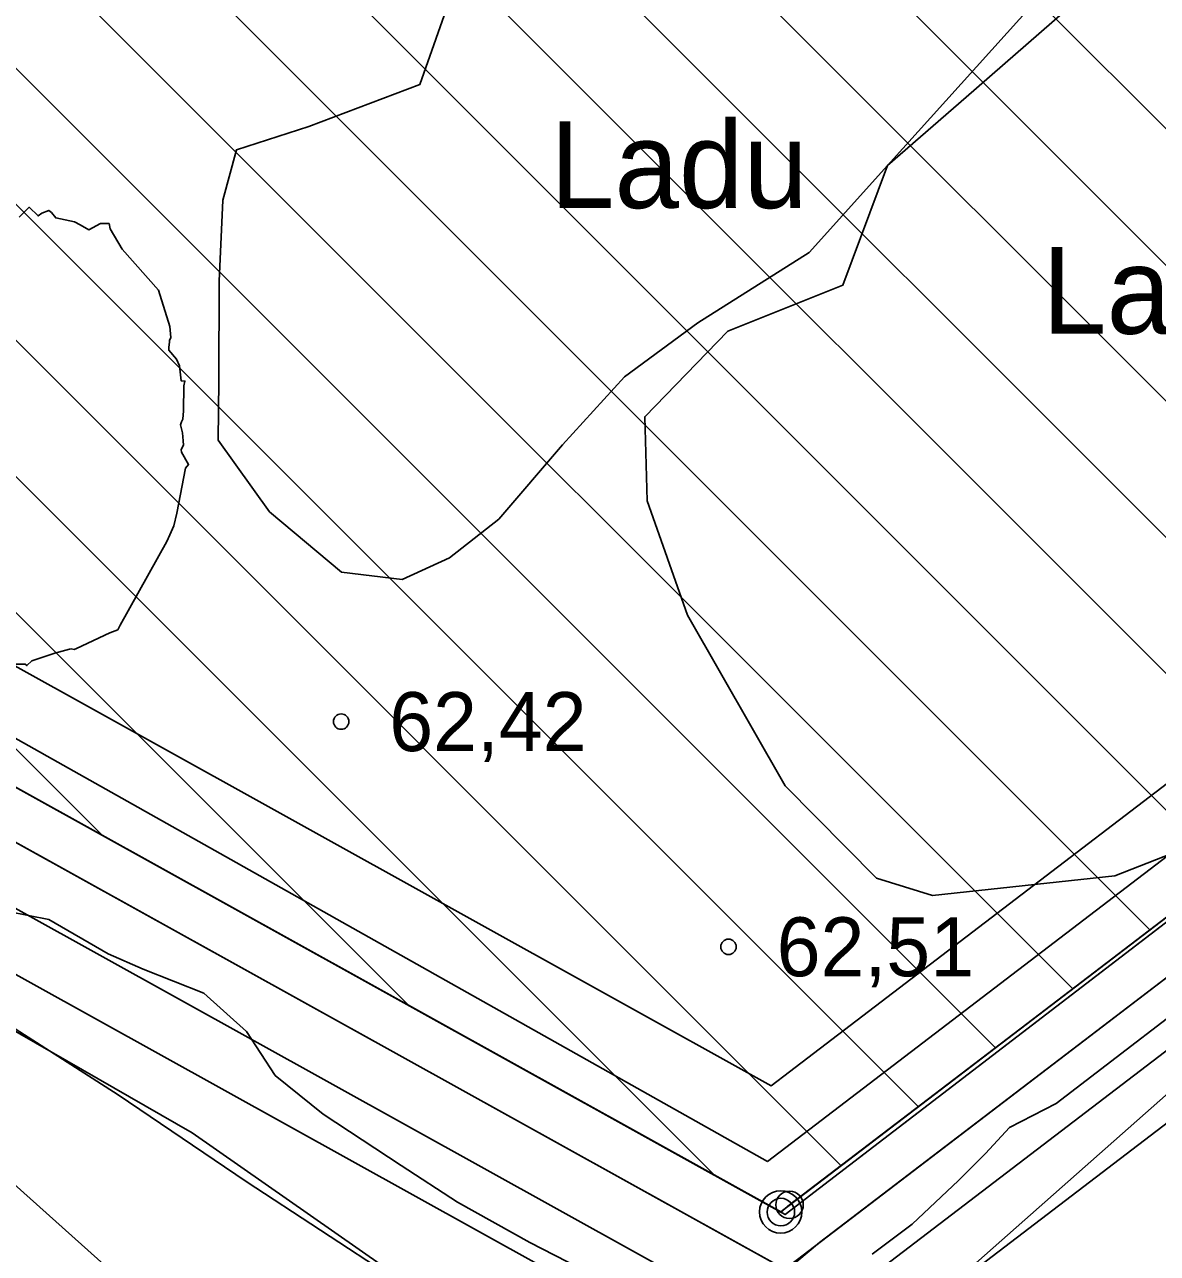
# Model space of a CAD drawing. Extents: x 532503 to 539665, y 6557663 to 6561526.
# Drawn here: x 535218.7 to 535265.8, y 6559649.2 to 6559700.3 of the extents above; entities that cross this region are included whole.
import ezdxf

# ---------------------------------------------------------------- set-up
doc = ezdxf.new("R2010")
doc.units = 0
for name, color, linetype in [('HALJASTUS', 7, 'Continuous'), ('illumineerimisjooned', 7, 'Continuous'), ('Kaevandatud ala', 7, 'Continuous'), ('kataster', 7, 'Continuous'), ('KORGUS-EH2000', 7, 'Continuous'), ('ME_aktiivne', 7, 'Continuous'), ('PIIR', 7, 'Continuous'), ('PIIR_me', 7, 'Continuous'), ('PIIRIMLEITUD', 7, 'Continuous'), ('Plokid', 7, 'Continuous'), ('RELJEEF', 7, 'Continuous'), ('RELJEEF 1', 7, 'Continuous'), ('TEE', 7, 'Continuous'), ('TM_aktiivne', 7, 'Continuous')]:
    doc.layers.add(name, color=color, linetype=linetype)

msp = doc.modelspace()

# ---------------------------------------------------------------- linework, layer by layer
at = {"layer": 'illumineerimisjooned'}
for points in [[(534195.15, 6559981.187), (534198.982, 6559981.551), (535160.123, 6560071.768), (535418.528, 6559993.818), (535458.873, 6559929.252), (535494.628, 6559867.696), (535482.599, 6559826.001), (535251.738, 6559649.676), (535250.358, 6559648.526), (535180.445, 6559687.333), (534941.147, 6559814.594), (534876.935, 6559774.719), (534959.617, 6559531.323), (534733.77, 6559483.152), (534375.905, 6559461.866), (534195.514, 6559444.474)], [(535136.963, 6559567.806), (535183.61, 6559682.831), (535250.501, 6559645.706), (535253.17, 6559647.743), (535476.016, 6559817.954)]]:
    msp.add_lwpolyline(points, dxfattribs=at)
for points in [[(534967.673, 6560049.69), (534974.155, 6559828.082), (535058.693, 6559883.051), (535223.499, 6560002.448), (535218.56, 6560049.918), (535415.933, 6559990.422), (535455.447, 6559927.188), (535490.312, 6559867.164), (535479.121, 6559828.379), (535249.574, 6559653.049), (535182.36, 6559690.845), (534940.993, 6559819.216), (534872.135, 6559776.441), (534954.369, 6559534.338), (534950.911, 6559533.67), (534733.22, 6559487.117), (534375.585, 6559465.864), (534199.951, 6559448.922), (533951.788, 6559660.129), (534200.214, 6559977.649), (534931.627, 6560046.309)], [(535537.644, 6559868.04), (535535.932, 6559811.278), (535531.57, 6559735.34), (535531.4, 6559680.476), (535535.969, 6559621.33), (535541.688, 6559571.196), (535546.449, 6559503.997), (535276.396, 6559543.285), (535107.957, 6559502.648), (535182.405, 6559686.245), (535250.294, 6559648.566)]]:
    msp.add_lwpolyline(points, close=True, dxfattribs=at)
at = {"layer": 'Kaevandatud ala'}
for p, q in [((535250.5, 6559651.24), (535480.86, 6559827.19)), ((535184.457, 6559777.613), (535284.704, 6559677.366)), ((535182.417, 6559773.996), (535281.497, 6559674.916)), ((535180.416, 6559770.341), (535278.29, 6559672.466)), ((535166.863, 6559766.922), (535268.668, 6559665.117)), ((535178.444, 6559766.656), (535275.083, 6559670.017)), ((535176.48, 6559762.963), (535271.876, 6559667.567)), ((535171.315, 6559756.814), (535265.461, 6559662.668)), ((535150.863, 6559754.638), (535252.632, 6559652.869)), ((535156.535, 6559754.623), (535255.84, 6559655.319)), ((535134.478, 6559754.053), (535221.942, 6559666.589)), ((535140.666, 6559753.522), (535234.654, 6559659.534)), ((535145.883, 6559753.962), (535247.366, 6559652.478)), ((535168.701, 6559753.77), (535262.254, 6559660.218)), ((535163.688, 6559753.127), (535259.047, 6559657.768))]:
    msp.add_line(p, q, dxfattribs=at)
msp.add_lwpolyline([(535181.4, 6559689.09), (535250.12, 6559650.95), (535250.5, 6559651.24)], dxfattribs=at)
at = {"layer": 'kataster'}
for points in [[(533947.7, 6559658.95), (533949.2, 6559955.8), (534198.28, 6559979.48), (535159.89, 6560069.73), (535417.31, 6559992.13), (535457.22, 6559928.24), (535504.86, 6559846.09), (535250.3, 6559650.84), (535181.52, 6559689.04), (534941.15, 6559817.08), (534874.65, 6559775.26), (534957.01, 6559532.73), (534735.22, 6559485.45), (534375.71, 6559463.85), (534199.28, 6559446.9), (534122.84, 6559439.44), (534110.45, 6559447.36), (534092.53, 6559453.94), (534085.13, 6559454.75)], [(535538.05, 6559871.58), (535539.27, 6559872.49), (535541.59, 6559874.28), (535537.93, 6559811.19), (535533.57, 6559735.28), (535533.4, 6559680.55), (535537.96, 6559621.52), (535543.68, 6559571.38), (535548.62, 6559501.66), (535276.49, 6559541.25), (535104.64, 6559499.79), (535181.52, 6559689.04), (535250.3, 6559650.84), (535504.86, 6559846.09)]]:
    msp.add_lwpolyline(points, close=True, dxfattribs=at)
at = {"layer": 'KORGUS-EH2000'}
for centre in [(535231.86, 6559671.32), (535247.954, 6559661.965)]:
    msp.add_circle(centre, 0.32, dxfattribs=at)
at = {"layer": 'ME_aktiivne'}
msp.add_lwpolyline([(535181.4, 6559689.09), (535250.12, 6559650.95), (535250.5, 6559651.24), (535480.86, 6559827.19), (535473.59, 6559802.83), (535506.03, 6559511.29), (535131.71, 6559566.56)], close=True, dxfattribs=at)
at = {"layer": 'PIIR'}
msp.add_circle((535250.12, 6559650.95), 0.88, dxfattribs=at)
msp.add_circle((535250.12, 6559650.95), 0.88, dxfattribs=at)
msp.add_circle((535250.12, 6559650.95), 0.88, dxfattribs=at)
msp.add_circle((535250.12, 6559650.95), 0.88, dxfattribs=at)
msp.add_circle((535250.12, 6559650.95), 0.88, dxfattribs=at)
at = {"layer": 'PIIR_me'}
msp.add_lwpolyline([(534441.63, 6560002.32), (534688.17, 6560025.46), (534931.44, 6560048.3), (534969.61, 6560051.877), (534976.05, 6559831.7), (535057.56, 6559884.7), (535221.39, 6560003.39), (535216.26, 6560052.7), (535417.23, 6559992.12), (535457.16, 6559928.22), (535492.47, 6559867.43), (535480.86, 6559827.19), (535250.12, 6559650.95), (535250.12, 6559650.95), (535181.4, 6559689.09), (534941.07, 6559816.91), (534874.54, 6559775.58), (534957, 6559532.81), (534951.31, 6559531.71), (534733.49, 6559485.13), (534485.11, 6559470.37)], dxfattribs=at)
at = {"layer": 'PIIRIMLEITUD'}
for centre in [(535250.13, 6559650.945), (535250.49, 6559651.245)]:
    msp.add_circle(centre, 0.57, dxfattribs=at)
at = {"layer": 'Plokid'}
for points in [[(535473.831, 6559827.358), (535249.729, 6559656.195), (535183.501, 6559692.956), (534940.9, 6559821.974), (534869.24, 6559777.474), (534950.465, 6559538.369)], [(535141.263, 6559572.023), (535184.815, 6559679.417), (535250.709, 6559642.846), (535254.626, 6559645.835), (535468.361, 6559809.086)]]:
    msp.add_lwpolyline(points, dxfattribs=at)
at = {"layer": 'RELJEEF'}
for points in [[(535270.979, 6559705.221), (535261.928, 6559700.833), (535257.824, 6559697.263), (535254.556, 6559694.425), (535252.708, 6559689.45), (535247.92, 6559687.545), (535244.474, 6559683.984), (535244.577, 6559680.494), (535246.247, 6559675.742), (535250.312, 6559668.654), (535254.096, 6559664.821), (535256.427, 6559664.093), (535264.001, 6559664.919), (535268.413, 6559666.649)], [(535270.979, 6559705.221), (535261.928, 6559700.833), (535257.824, 6559697.263), (535254.556, 6559694.425), (535252.708, 6559689.45), (535247.92, 6559687.545), (535244.474, 6559683.984), (535244.577, 6559680.494), (535246.247, 6559675.742), (535250.312, 6559668.654), (535254.096, 6559664.821), (535256.427, 6559664.093), (535264.001, 6559664.919), (535268.413, 6559666.649)], [(535236.478, 6559701.606), (535235.126, 6559697.784), (535230.52, 6559696.046), (535227.513, 6559695.08), (535226.948, 6559692.985), (535226.792, 6559689.626), (535226.786, 6559685.479), (535226.759, 6559683.011), (535228.891, 6559680.03), (535231.877, 6559677.536), (535234.401, 6559677.219), (535236.358, 6559678.13), (535238.408, 6559679.738), (535241.063, 6559682.82), (535243.629, 6559685.642), (535246.681, 6559687.884), (535251.298, 6559690.813), (535254.556, 6559694.425), (535261.315, 6559701.937)], [(535236.478, 6559701.606), (535235.126, 6559697.784), (535230.52, 6559696.046), (535227.513, 6559695.08), (535226.948, 6559692.985), (535226.792, 6559689.626), (535226.786, 6559685.479), (535226.759, 6559683.011), (535228.891, 6559680.03), (535231.877, 6559677.536), (535234.401, 6559677.219), (535236.358, 6559678.13), (535238.408, 6559679.738), (535241.063, 6559682.82), (535243.629, 6559685.642), (535246.681, 6559687.884), (535251.298, 6559690.813), (535254.556, 6559694.425), (535261.315, 6559701.937)], [(535218.481, 6559692.28), (535218.897, 6559692.692), (535219.274, 6559692.331), (535219.433, 6559692.446), (535219.715, 6559692.557), (535219.831, 6559692.472), (535220.002, 6559692.247), (535220.78, 6559692.087), (535221.02, 6559691.962), (535221.376, 6559691.758), (535221.861, 6559692.011), (535222.221, 6559692.012), (535222.267, 6559691.797), (535222.766, 6559690.947), (535224.279, 6559689.247), (535224.742, 6559687.734), (535224.779, 6559687.278), (535224.731, 6559687.159), (535224.735, 6559687.102), (535224.696, 6559686.868), (535224.705, 6559686.754), (535225.023, 6559686.384), (535225.143, 6559686.096), (535225.209, 6559685.483), (535225.373, 6559685.467), (535225.322, 6559685.265), (535225.311, 6559684.235), (535225.285, 6559683.884), (535225.234, 6559683.772), (535225.185, 6559683.654), (535225.272, 6559683.319), (535225.3, 6559682.979), (535225.315, 6559682.809), (535225.215, 6559682.63), (535225.225, 6559682.516), (535225.523, 6559682.007), (535225.396, 6559681.845), (535225.038, 6559679.987), (535224.911, 6559679.46), (535224.745, 6559679.078), (535224.623, 6559678.801), (535222.682, 6559675.321), (535222.582, 6559675.139), (535222.251, 6559675.002), (535220.869, 6559674.356), (535220.776, 6559674.311), (535220.642, 6559674.341), (535220.576, 6559674.327), (535219.966, 6559674.164), (535219.009, 6559673.842), (535218.805, 6559673.651), (535218.732, 6559673.712), (535218.157, 6559673.71)], [(535159.942, 6559690.567), (535165.615, 6559688.105), (535172.198, 6559684.334), (535181.03, 6559680.447), (535186.026, 6559676.801), (535195.032, 6559671.856), (535204.455, 6559665.98), (535216.544, 6559659.476), (535225.667, 6559654.234), (535233.623, 6559648.686), (535240.733, 6559644.378), (535245.7, 6559642.439), (535250.352, 6559642.911), (535252.247, 6559643.69), (535257.402, 6559648.085), (535276.49, 6559664.974), (535283.65, 6559669.546), (535296.525, 6559679.142), (535302.634, 6559683.081), (535307.233, 6559681.152), (535312.048, 6559676.87), (535313.569, 6559675.416), (535312.457, 6559672.141), (535309.515, 6559669.568)], [(535159.942, 6559690.567), (535165.615, 6559688.105), (535172.198, 6559684.334), (535181.03, 6559680.447), (535186.026, 6559676.801), (535195.032, 6559671.856), (535204.455, 6559665.98), (535216.544, 6559659.476), (535225.667, 6559654.234), (535233.623, 6559648.686), (535240.733, 6559644.378), (535245.7, 6559642.439), (535250.352, 6559642.911), (535252.247, 6559643.69), (535257.402, 6559648.085), (535276.49, 6559664.974), (535283.65, 6559669.546), (535296.525, 6559679.142), (535302.634, 6559683.081), (535307.233, 6559681.152), (535312.048, 6559676.87), (535313.569, 6559675.416), (535312.457, 6559672.141), (535309.515, 6559669.568)], [(535253.914, 6559649.201), (535255.576, 6559650.444), (535257.502, 6559652.26), (535258.624, 6559653.371), (535259.621, 6559654.458), (535261.56, 6559655.454), (535268.864, 6559661.043), (535271.488, 6559663.701), (535273.729, 6559666.159), (535276.059, 6559668.413), (535277.306, 6559669.273), (535278.967, 6559669.813), (535281.252, 6559671.586), (535282.015, 6559672.997), (535283.649, 6559673.59), (535284.552, 6559674.252), (535285.756, 6559675.168), (535287.329, 6559676.323)], [(535253.914, 6559649.201), (535255.576, 6559650.444), (535257.502, 6559652.26), (535258.624, 6559653.371), (535259.621, 6559654.458), (535261.56, 6559655.454), (535268.864, 6559661.043), (535271.488, 6559663.701), (535273.729, 6559666.159), (535276.059, 6559668.413), (535277.306, 6559669.273), (535278.967, 6559669.813), (535281.252, 6559671.586), (535282.015, 6559672.997), (535283.649, 6559673.59), (535284.552, 6559674.252), (535285.756, 6559675.168), (535287.329, 6559676.323)], [(535218.023, 6559663.428), (535219.721, 6559663.102), (535222.177, 6559661.675), (535223.63, 6559661.029), (535226.161, 6559660.042), (535227.935, 6559658.447), (535229.121, 6559656.621), (535231.116, 6559655.009), (535234.354, 6559652.882), (535236.697, 6559651.356), (535239.701, 6559649.679), (535241.78, 6559648.609)], [(535218.023, 6559663.428), (535219.721, 6559663.102), (535222.177, 6559661.675), (535223.63, 6559661.029), (535226.161, 6559660.042), (535227.935, 6559658.447), (535229.121, 6559656.621), (535231.116, 6559655.009), (535234.354, 6559652.882), (535236.697, 6559651.356), (535239.701, 6559649.679), (535241.78, 6559648.609)]]:
    msp.add_lwpolyline(points, dxfattribs=at)
at = {"layer": 'RELJEEF 1'}
msp.add_lwpolyline([(535217.607, 6559659.005), (535222.596, 6559655.81), (535227.915, 6559652.22), (535234.097, 6559648.166)], dxfattribs=at)
at = {"layer": 'TEE'}
msp.add_lwpolyline([(535251.165, 6559629.144), (535239.122, 6559635.951), (535225.341, 6559645.775), (535206.128, 6559662.973), (535191.432, 6559672.777), (535180.426, 6559679.135), (535154.139, 6559686.829), (535139.55, 6559684.77)], dxfattribs=at)
at = {"layer": 'TM_aktiivne'}
for points in [[(535159.92, 6560069.74), (535417.23, 6559992.12), (535457.16, 6559928.22), (535492.47, 6559867.43), (535480.86, 6559827.19), (535250.49, 6559651.24), (535250.13, 6559650.94), (535181.4, 6559689.09), (534941.07, 6559816.9), (534874.53, 6559775.58), (534957, 6559532.81), (534733.5, 6559485.14), (534375.75, 6559463.86), (534199.32, 6559446.85), (534124.95, 6559439.68), (533949.03, 6559659.85), (533949.15, 6559955.79), (534199.17, 6559979.56)], [(535539.77, 6559872.18), (535537.93, 6559811.19), (535533.57, 6559735.28), (535533.4, 6559680.55), (535537.96, 6559621.52), (535543.68, 6559571.38), (535548.62, 6559501.66), (535276.49, 6559541.25), (535104.64, 6559499.79), (535181.4, 6559689.09), (535250.12, 6559650.95)]]:
    msp.add_lwpolyline(points, close=True, dxfattribs=at)

# ---------------------------------------------------------------- texts
at = {"layer": 'HALJASTUS'}
for p in [(535240.539, 6559692.656), (535260.982, 6559687.434), (535260.982, 6559687.434)]:
    msp.add_text('Ladu', height=3.6, dxfattribs=at).set_placement(p)
at = {"layer": 'KORGUS-EH2000'}
for s, p in [('62,42 ', (535233.86, 6559670.095)), ('62,51 ', (535249.954, 6559660.74))]:
    msp.add_text(s, height=2.45, dxfattribs=at).set_placement(p)

doc.saveas('drawing.dxf')
